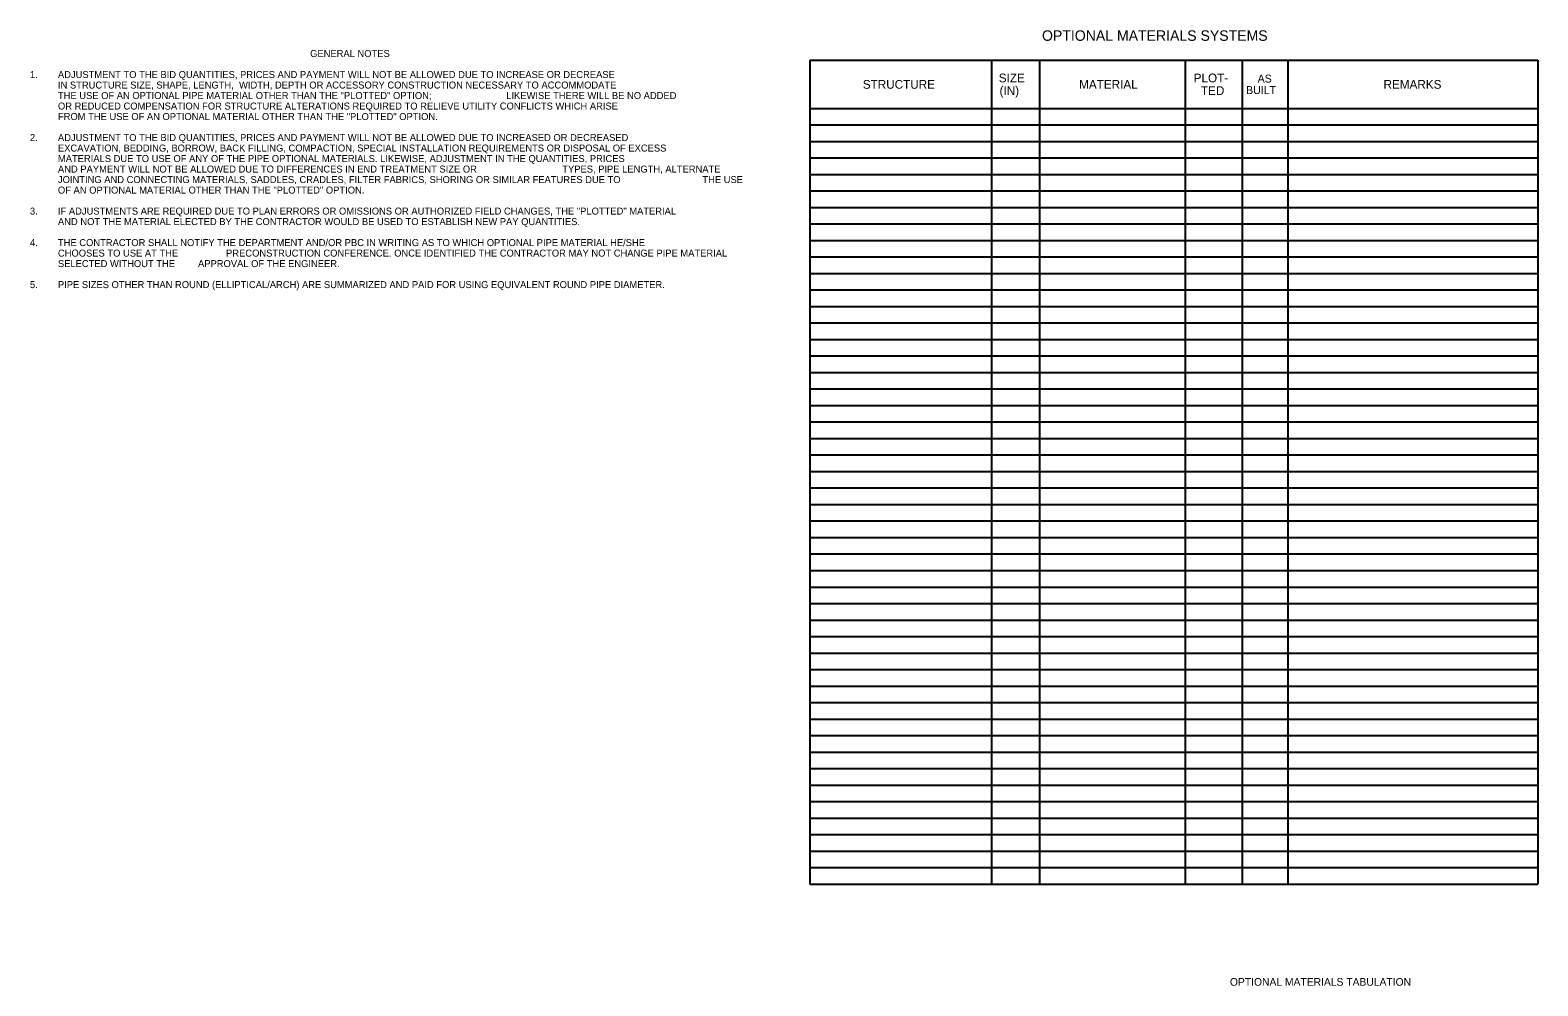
# Model space of a CAD drawing. Extents: x 0.2 to 15.3, y -0.2 to 9.3.
import ezdxf

# ---------------------------------------------------------------- set-up
doc = ezdxf.new("R2010")
doc.units = 0
for name, color, linetype in [('Default', 7, 'Continuous'), ('SumBoxBorder_dp', 7, 'Continuous'), ('SumBoxLines_dp', 7, 'Continuous'), ('SumBoxLinesMin_dp', 7, 'Continuous'), ('TextLabel', 7, 'Continuous')]:
    doc.layers.add(name, color=color, linetype=linetype)

msp = doc.modelspace()

# ---------------------------------------------------------------- linework, layer by layer
at = {"layer": 'SumBoxBorder_dp'}
for p, q in [((7.98, 9.024), (15.255, 9.024)), ((7.98, 9.024), (7.98, 0.789)), ((15.255, 9.024), (15.255, 0.789)), ((7.98, 0.789), (15.255, 0.789))]:
    msp.add_line(p, q, dxfattribs=at)
at = {"layer": 'SumBoxLines_dp'}
for p, q in [((9.795, 9.024), (9.795, 8.544)), ((9.795, 9.024), (9.795, 0.789)), ((10.275, 9.024), (10.275, 0.789)), ((10.275, 9.024), (10.275, 0.789)), ((11.73, 9.024), (11.73, 0.789)), ((11.73, 9.024), (11.73, 0.789)), ((12.3, 9.024), (12.3, 0.789)), ((12.3, 9.024), (12.3, 0.789)), ((12.758, 9.024), (12.758, 0.789)), ((12.758, 9.024), (12.758, 0.789)), ((7.98, 8.544), (15.255, 8.544)), ((7.98, 8.544), (15.255, 8.544))]:
    msp.add_line(p, q, dxfattribs=at)
at = {"layer": 'SumBoxLinesMin_dp'}
for p, q in [((7.98, 8.379), (15.255, 8.379)), ((7.98, 8.379), (15.255, 8.379)), ((7.98, 8.214), (15.255, 8.214)), ((7.98, 8.214), (15.255, 8.214)), ((7.98, 8.049), (15.255, 8.049)), ((7.98, 8.049), (15.255, 8.049)), ((7.98, 7.884), (15.255, 7.884)), ((7.98, 7.884), (15.255, 7.884)), ((7.98, 7.719), (15.255, 7.719)), ((7.98, 7.719), (15.255, 7.719)), ((7.98, 7.554), (15.255, 7.554)), ((7.98, 7.554), (15.255, 7.554)), ((7.98, 7.389), (15.255, 7.389)), ((7.98, 7.389), (15.255, 7.389)), ((7.98, 7.224), (15.255, 7.224)), ((7.98, 7.224), (15.255, 7.224)), ((7.98, 7.059), (15.255, 7.059)), ((7.98, 7.059), (15.255, 7.059)), ((7.98, 6.894), (15.255, 6.894)), ((7.98, 6.894), (15.255, 6.894)), ((7.98, 6.729), (15.255, 6.729)), ((7.98, 6.729), (15.255, 6.729)), ((7.98, 6.564), (15.255, 6.564)), ((7.98, 6.564), (15.255, 6.564)), ((7.98, 6.399), (15.255, 6.399)), ((7.98, 6.399), (15.255, 6.399)), ((7.98, 6.234), (15.255, 6.234)), ((7.98, 6.234), (15.255, 6.234)), ((7.98, 6.069), (15.255, 6.069)), ((7.98, 6.069), (15.255, 6.069)), ((7.98, 5.904), (15.255, 5.904)), ((7.98, 5.904), (15.255, 5.904)), ((7.98, 5.739), (15.255, 5.739)), ((7.98, 5.739), (15.255, 5.739)), ((7.98, 5.574), (15.255, 5.574)), ((7.98, 5.574), (15.255, 5.574)), ((7.98, 5.409), (15.255, 5.409)), ((7.98, 5.409), (15.255, 5.409)), ((7.98, 5.244), (15.255, 5.244)), ((7.98, 5.244), (15.255, 5.244)), ((7.98, 5.079), (15.255, 5.079)), ((7.98, 5.079), (15.255, 5.079)), ((7.98, 4.914), (15.255, 4.914)), ((7.98, 4.914), (15.255, 4.914)), ((7.98, 4.749), (15.255, 4.749)), ((7.98, 4.749), (15.255, 4.749)), ((7.98, 4.584), (15.255, 4.584)), ((7.98, 4.584), (15.255, 4.584)), ((7.98, 4.419), (15.255, 4.419)), ((7.98, 4.419), (15.255, 4.419)), ((7.98, 4.254), (15.255, 4.254)), ((7.98, 4.254), (15.255, 4.254)), ((7.98, 4.089), (15.255, 4.089)), ((7.98, 4.089), (15.255, 4.089)), ((7.98, 3.924), (15.255, 3.924)), ((7.98, 3.924), (15.255, 3.924)), ((7.98, 3.759), (15.255, 3.759)), ((7.98, 3.759), (15.255, 3.759)), ((7.98, 3.594), (15.255, 3.594)), ((7.98, 3.594), (15.255, 3.594)), ((7.98, 3.429), (15.255, 3.429)), ((7.98, 3.429), (15.255, 3.429)), ((7.98, 3.264), (15.255, 3.264)), ((7.98, 3.264), (15.255, 3.264)), ((7.98, 3.099), (15.255, 3.099)), ((7.98, 3.099), (15.255, 3.099)), ((7.98, 2.934), (15.255, 2.934)), ((7.98, 2.934), (15.255, 2.934)), ((7.98, 2.769), (15.255, 2.769)), ((7.98, 2.769), (15.255, 2.769)), ((7.98, 2.604), (15.255, 2.604)), ((7.98, 2.604), (15.255, 2.604)), ((7.98, 2.439), (15.255, 2.439)), ((7.98, 2.439), (15.255, 2.439)), ((7.98, 2.274), (15.255, 2.274)), ((7.98, 2.274), (15.255, 2.274)), ((7.98, 2.109), (15.255, 2.109)), ((7.98, 2.109), (15.255, 2.109)), ((7.98, 1.944), (15.255, 1.944)), ((7.98, 1.944), (15.255, 1.944)), ((7.98, 1.779), (15.255, 1.779)), ((7.98, 1.779), (15.255, 1.779)), ((7.98, 1.614), (15.255, 1.614)), ((7.98, 1.614), (15.255, 1.614)), ((7.98, 1.449), (15.255, 1.449)), ((7.98, 1.449), (15.255, 1.449)), ((7.98, 1.284), (15.255, 1.284)), ((7.98, 1.284), (15.255, 1.284)), ((7.98, 1.119), (15.255, 1.119)), ((7.98, 1.119), (15.255, 1.119)), ((7.98, 0.954), (15.255, 0.954)), ((7.98, 0.954), (15.255, 0.954))]:
    msp.add_line(p, q, dxfattribs=at)

# ---------------------------------------------------------------- texts
at = {"layer": 'Default'}
msp.add_text('OPTIONAL MATERIALS TABULATION', height=0.07709, dxfattribs=at).set_placement((12.178, -0.227))
at = {"layer": 'TextLabel'}
for s, height, p in [('OPTIONAL MATERIALS SYSTEMS', 0.105, (10.3, 9.219)), ('GENERAL NOTES ', 0.07, (2.986, 9.057)), ('1.', 0.07, (0.186, 8.847)), ('ADJUSTMENT TO THE BID QUANTITIES, PRICES AND PAYMENT WILL NOT BE ALLOWED DUE TO INCREASE OR DECREASE ', 0.07, (0.466, 8.847)), ('SIZE', 0.0875, (9.868, 8.804)), ('PLOT-', 0.0875, (11.816, 8.804)), ('IN STRUCTURE SIZE, SHAPE, LENGTH,  WIDTH, DEPTH OR ACCESSORY CONSTRUCTION NECESSARY TO ACCOMMODATE ', 0.07, (0.466, 8.742)), ('STRUCTURE', 0.0875, (8.509, 8.74)), ('(IN)', 0.0875, (9.876, 8.677)), ('MATERIAL', 0.0875, (10.671, 8.74)), ('TED', 0.0875, (11.888, 8.677)), ('BUILT', 0.0788, (12.34, 8.687)), ('AS', 0.0788, (12.455, 8.802)), ('REMARKS', 0.0875, (13.713, 8.74)), ('THE USE OF AN OPTIONAL PIPE MATERIAL OTHER THAN THE "PLOTTED" OPTION; ', 0.07, (0.466, 8.637)), ('OR REDUCED COMPENSATION FOR STRUCTURE ALTERATIONS REQUIRED TO RELIEVE UTILITY CONFLICTS WHICH ARISE ', 0.07, (0.466, 8.532)), ('LIKEWISE THERE WILL BE NO ADDED ', 0.07, (4.946, 8.637)), ('FROM THE USE OF AN OPTIONAL MATERIAL OTHER THAN THE "PLOTTED" OPTION. ', 0.07, (0.466, 8.427)), ('2.', 0.07, (0.186, 8.217)), ('ADJUSTMENT TO THE BID QUANTITIES, PRICES AND PAYMENT WILL NOT BE ALLOWED DUE TO INCREASED OR DECREASED ', 0.07, (0.466, 8.217)), ('EXCAVATION, BEDDING, BORROW, BACK FILLING, COMPACTION, SPECIAL INSTALLATION REQUIREMENTS OR DISPOSAL OF EXCESS ', 0.07, (0.466, 8.112)), ('MATERIALS DUE TO USE OF ANY OF THE PIPE OPTIONAL MATERIALS. LIKEWISE, ADJUSTMENT IN THE QUANTITIES, PRICES ', 0.07, (0.466, 8.007)), ('AND PAYMENT WILL NOT BE ALLOWED DUE TO DIFFERENCES IN END TREATMENT SIZE OR ', 0.07, (0.466, 7.902)), ('JOINTING AND CONNECTING MATERIALS, SADDLES, CRADLES, FILTER FABRICS, SHORING OR SIMILAR FEATURES DUE TO ', 0.07, (0.466, 7.797)), ('TYPES, PIPE LENGTH, ALTERNATE ', 0.07, (5.506, 7.902)), ('THE USE ', 0.07, (6.906, 7.797)), ('OF AN OPTIONAL MATERIAL OTHER THAN THE "PLOTTED" OPTION. ', 0.07, (0.466, 7.692)), ('3. ', 0.07, (0.186, 7.482)), ('IF ADJUSTMENTS ARE REQUIRED DUE TO PLAN ERRORS OR OMISSIONS OR AUTHORIZED FIELD CHANGES, THE "PLOTTED" MATERIAL ', 0.07, (0.466, 7.482)), ('AND NOT THE MATERIAL ELECTED BY THE CONTRACTOR WOULD BE USED TO ESTABLISH NEW PAY QUANTITIES. ', 0.07, (0.466, 7.377)), ('4. ', 0.07, (0.186, 7.167)), ('THE CONTRACTOR SHALL NOTIFY THE DEPARTMENT AND/OR PBC IN WRITING AS TO WHICH OPTIONAL PIPE MATERIAL HE/SHE ', 0.07, (0.466, 7.167)), ('CHOOSES TO USE AT THE ', 0.07, (0.466, 7.062)), ('PRECONSTRUCTION CONFERENCE. ONCE IDENTIFIED THE CONTRACTOR MAY NOT CHANGE PIPE MATERIAL ', 0.07, (2.146, 7.062)), ('SELECTED WITHOUT THE ', 0.07, (0.466, 6.957)), ('APPROVAL OF THE ENGINEER. ', 0.07, (1.866, 6.957)), ('5. ', 0.07, (0.186, 6.747)), ('PIPE SIZES OTHER THAN ROUND (ELLIPTICAL/ARCH) ARE SUMMARIZED AND PAID FOR USING EQUIVALENT ROUND PIPE DIAMETER. ', 0.07, (0.466, 6.747))]:
    msp.add_text(s, height=height, dxfattribs=at).set_placement(p)

doc.saveas('drawing.dxf')
